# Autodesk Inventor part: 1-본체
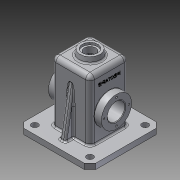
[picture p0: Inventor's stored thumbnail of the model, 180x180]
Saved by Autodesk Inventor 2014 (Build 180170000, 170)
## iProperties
Created: 2016-02
Part Number: 1-본체
Material: 알루미늄 6061
Document SubType Name: Modeling
Designer: D.Y.KIM
Density: 2.71 g/cm^3
Appearance: 알루미늄 - 평지
Mass: 926.895 g
Surface Area: 1038.71 cm^2
Volume: 342.028 cm^3
Author: D.Y.KIM
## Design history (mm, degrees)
sketch "스케치1"
  geometry: L1 (0, 0)-(-65, 0); L2 (-65, 0)-(-65, 10); L3 (-65, 10)-(0, 10); L4 (0, 10)-(0, 0)
  constraints: 8 end point, 2 parallel, 1 horizontal, 1 perpendicular
  dimensions: "d0" = 130 diameter of L2 L4; "d1" = 10 distance of L1.end L2.end
extrude "돌출1" new body sketch "스케치1" stored distance "d2" = 130; taper "d3" = 0 deg
chamfer "모따기1" distance "d4" = 10; stored, may be unused: second distance "d5" = 2, angle "d6" = 45 deg
sketch "스케치2"
  geometry: L1 (55, 0)-(0, 0) reference; L2 (0, 130)-(55, 130) reference; L3 (0, 130)-(0, 0) reference; 3 further points
  dimensions: "d7" = 15 distance from line of point (50, 15) L1; "d8" = 15 distance from line of L2 point (50, 115); "d9" = 50 horizontal distance of L1.end point (50, 15); "d10" = 50 distance from line of L3 point (50, 115)
hole "구멍1" sketch "스케치2" at (50, 15), (50, 115) diameter "d11" = 12; stored, may be unused: countersink angle "d15" = 90 deg, drill point angle "d17" = 118 deg; dims "d12" = 6, "d13" = 4, "d14" = 2, "d16" = 12
sketch "스케치3"
  geometry: L1 (-100, 90)-(-30, 90); L2 (-30, 90)-(-30, 20); L3 (-30, 20)-(-100, 20); L4 (-100, 20)-(-100, 90); 3 further points
  constraints: 8 end point, 2 midpoint, 2 parallel, 1 horizontal, 1 horizontal alignment, 1 perpendicular, 1 vertical alignment
  dimensions: "d18" = 70 distance of L1.start L1.end; "d19" = 70 distance of L3.end L1.start
extrude "돌출2" join sketch "스케치3" distance "d20" = 110; taper "d21" = 0 deg
feature "쉘1" dims "d22" = 10, "d23" = 5
fillet "모깎기1" dims "d24" = 8
fillet "모깎기2" dims "d25" = 3
fillet "모깎기3" dims "d26" = 8
fillet "모깎기4" dims "d27" = 3
sketch "스케치4"
  geometry: L1 (-35, 10)-(-35, 112) reference; L2 (-44, 10)-(-56, 10) reference; L3 (35, 112)-(35, 10) reference; L4 (56, 10)-(44, 10) reference; L5 (-35, 95.069)-(-50, 10); L6 (35, 95.069)-(50, 10); L7 (65, 0)-(65, 10) reference; L8 (-65, 10)-(-65, 0) reference; L9 (-50, 10)-(-35, 10); L10 (-35, 95.069)-(-35, 10); L11 (35, 95.069)-(35, 10); L12 (50, 10)-(35, 10); 1 further point
  constraints: 12 end point, 3 perpendicular, 2 midpoint, 2 point on line, 1 parallel
  dimensions: "d28" = 10 deg angle of L6 L7; "d29" = 10 deg angle of L5 L8
extrude "돌출3" join sketch "스케치4" stored distance "d30" = 10; taper "d31" = 0 deg
node "작업 평면1"
sketch "스케치5"
  geometry: L1 (55, 0)-(-55, 0) reference; C1 r 27.5 at (0, 55); 2 further points
  constraints: 1 centre point, 1 midpoint, 1 vertical alignment
  dimensions: "d33" = 55 diameter of C1; "d34" = 55 distance from line of L1 C1.centre
extrude "돌출4" join sketch "스케치5" stored distance "d35" = 10; taper "d36" = 0 deg
sketch "스케치6"
  geometry: C1 r 27.5 at (55, 27); 1 further point
  constraints: 1 centre point, 1 horizontal alignment
  dimensions: "d37" = 55 diameter of C1; "d38" = 55 distance of point (0, 27) C1.centre
extrude "돌출5" join sketch "스케치6" distance "d39" = 7; taper "d40" = -45 deg
hole "구멍2" diameter "d43" = 32; stored, may be unused: countersink angle "d47" = 90 deg, drill point angle "d49" = 0 deg; dims "d44" = 6, "d45" = 4, "d46" = 2, "d48" = 48, "d50" = 10, "d51" = 10
sketch "스케치7"
  geometry: C1 r 27.5 at (0, 0) reference; 2 further points
  constraints: 1 horizontal alignment
  dimensions: "d52" = 22.5 distance of point (-22.5, 0) C1.centre
hole "구멍3" sketch "스케치7" at (-22.5, 0) diameter "d53" = 3.242; stored, may be unused: countersink angle "d57" = 90 deg, drill point angle "d59" = 118 deg; dims "d54" = 8, "d55" = 4, "d56" = 2, "d58" = 10
fillet "모깎기5" dims "d63" = 0.5
chamfer "모따기2" distance "d64" = 1; stored, may be unused: second distance "d65" = 2, angle "d66" = 45 deg
sketch "스케치8"
  geometry: C1 r 20 at (-65, 55); 1 further point
  constraints: 1 centre point, 1 coincident
  dimensions: "d67" = 40 diameter of C1
extrude "돌출6" join sketch "스케치8" distance "d68" = 10; taper "d69" = -10 deg
hole "구멍4" diameter "d72" = 21; stored, may be unused: countersink angle "d76" = 90 deg, drill point angle "d78" = 118 deg; dims "d70" = 10, "d71" = 10, "d73" = 8, "d74" = 28, "d75" = 4, "d77" = 30
sketch "스케치9"
  geometry: L1 (12.188, 6.261)-(12.188, 47.739); L2 (12.188, 47.739)-(11.812, 47.739); L3 (11.812, 47.739)-(11.812, 6.261); L4 (11.812, 6.261)-(12.188, 6.261); L5 (102, 62)-(0, 62) reference; L6 (-18, 8.763)-(-18, 45.237) reference; 3 further points
  constraints: 2 midpoint, 2 other
  dimensions: "d79" = 35 distance from line of L5 point (12.188, 27); "d80" = 30 distance from line of L6 point (12, 47.739)
feature "엠보싱1" sketch "스케치9" dims "d0" = 130, "d1" = 10, "d81" = 0.5, "d82" = 0
fillet "모깎기6" dims "d83" = 3
fillet "모깎기7" dims "d84" = 3
fillet "모깎기8" dims "d85" = 3
fillet "모깎기9" dims "d86" = 3
fillet "모깎기10" dims "d87" = 0.5
node "솔리드1"
mirror "대칭1"
pattern_circular "원형 패턴1" dims angle "d61" = 360 deg
mirror "대칭2"
other parameters: "d32" = 48
